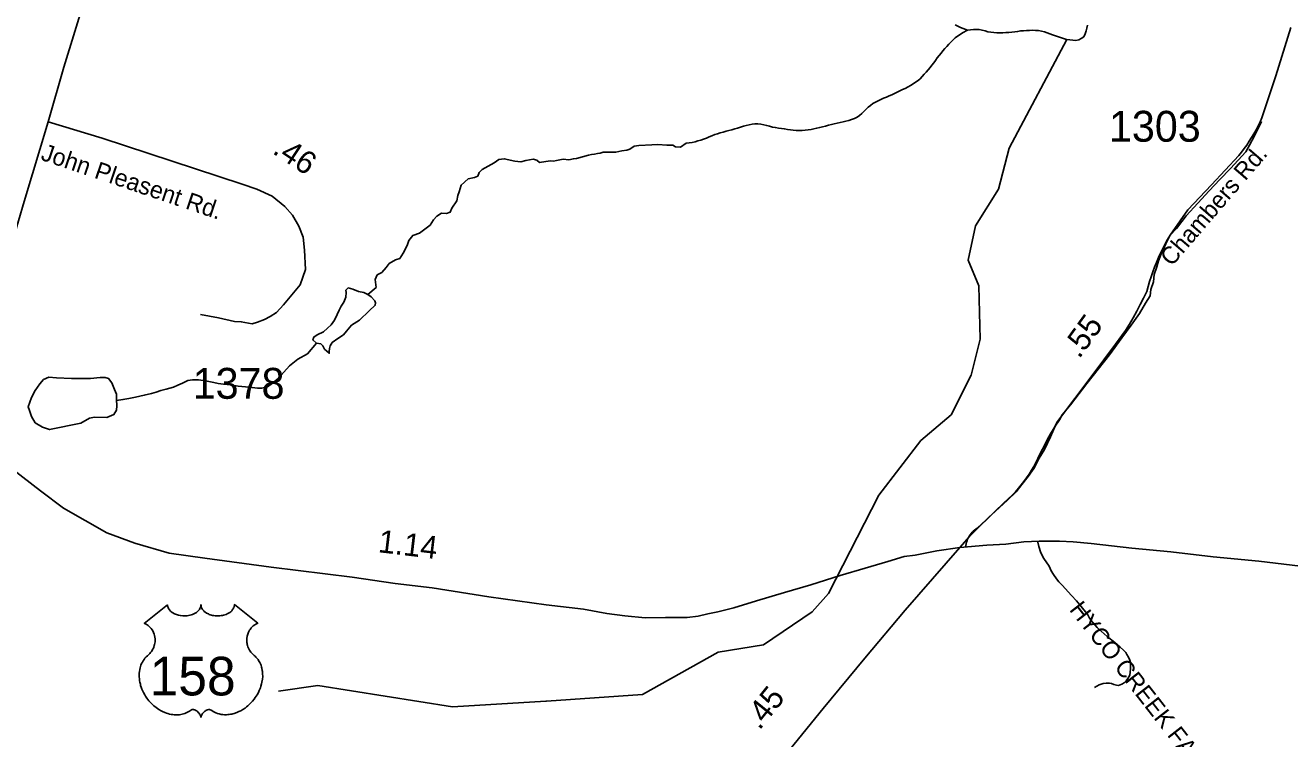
# Model space of a CAD drawing. Extents: x 1950930 to 2061844, y 904556 to 1017002.
# Drawn here: x 1960412 to 1967375, y 958442 to 962369 of the extents above; entities that cross this region are included whole.
import ezdxf

# ---------------------------------------------------------------- set-up
doc = ezdxf.new("R2010")
doc.units = 0
for name, color, linetype in [('Exist Hydrographic Creek Single Shore', 7, 'Continuous'), ('Exist Hydrographic Misc Water Feature', 7, 'Continuous'), ('Exist Road Non-System Type 51', 7, 'Continuous'), ('Exist Road Non-System Type 51 Label', 7, 'Continuous'), ('Exist Road Primary US Attributed', 7, 'Continuous'), ('Exist Road Primary US Mileage Hundredths English Label', 7, 'Continuous'), ('Exist Road Primary US Shield CELL', 7, 'Continuous'), ('Exist Road Primary US Shield Number Label', 7, 'Continuous'), ('Exist Road Primary US Structure Standard Bridge CELL', 7, 'Continuous'), ('Exist Road Secondary Type 41 Attributed', 7, 'Continuous'), ('Exist Road Secondary Type 51 Attributed', 7, 'Continuous'), ('Exist Road Secondary Type 51 Label', 7, 'Continuous'), ('Exist Road Secondary Type 51 Number Label', 7, 'Continuous')]:
    doc.layers.add(name, color=color, linetype=linetype)

msp = doc.modelspace()

# ---------------------------------------------------------------- linework, layer by layer
at = {"layer": 'Exist Hydrographic Creek Single Shore'}
for points in [[(1965531.7, 962371), (1965546.6, 962364.2), (1965561.6, 962357.3), (1965577, 962351.2), (1965599.7, 962343.4)], [(1966260.4, 962369.9), (1966257.1, 962353.5), (1966254.1, 962338), (1966248.5, 962322.6), (1966241.8, 962305.4)], [(1963281.4, 958649.7), (1963810.3, 958684.7), (1964227.3, 958918.9), (1964477.3, 958959.7), (1964744.3, 959141.3), (1964835.3, 959241.2), (1965111.3, 959783.6), (1965344.3, 960084.1), (1965511.4, 960225), (1965620.3, 960442.6), (1965670.3, 960641.8), (1965662.3, 960934.2), (1965603.2, 961076.5), (1965645.3, 961265.9), (1965770.3, 961466.8), (1965829.4, 961692.1), (1966147.8, 962290.9)], [(1965094.1, 961946), (1965108.8, 961954), (1965123.4, 961961), (1965138.6, 961967.3), (1965153.6, 961974.3), (1965168.9, 961980.5), (1965184.1, 961986.8), (1965198.9, 961993.9), (1965213.6, 962001), (1965228.4, 962008.1), (1965243.2, 962015.2), (1965258.1, 962022.1), (1965272.9, 962030.1), (1965287, 962038), (1965301.4, 962046.8), (1965314.9, 962055.5), (1965328, 962065.1), (1965339.9, 962075.5), (1965351.6, 962087.6), (1965362.7, 962099.7), (1965373.2, 962111.8), (1965383.8, 962124.7), (1965394.1, 962137.6), (1965404.5, 962150.4), (1965414.8, 962163.4), (1965424.6, 962176.3), (1965434.1, 962190.1), (1965443.9, 962203), (1965454.6, 962215.9), (1965465, 962228), (1965475.7, 962240.8), (1965487, 962252.9), (1965498, 962265), (1965509.3, 962277.1), (1965520.8, 962288.4), (1965532.7, 962299.6), (1965545.4, 962310), (1965559.3, 962318.8), (1965573.7, 962327.5), (1965599.7, 962343.4)], [(1965599.7, 962343.4), (1965616.4, 962344.6), (1965632.6, 962345.9), (1965649, 962346.4), (1965665.2, 962345.3), (1965681.1, 962341.6), (1965697.3, 962338), (1965713.1, 962333.6), (1965729.3, 962330.9), (1965745.7, 962329.6), (1965762.1, 962328.5), (1965778.5, 962328.2), (1965795, 962328.6), (1965811.4, 962329.1), (1965827.8, 962329.6), (1965844, 962330.9), (1965860.6, 962333), (1965876.8, 962336), (1965893, 962338), (1965909.2, 962339.4), (1965925.6, 962340.7), (1965942, 962341.2), (1965958.6, 962341.7), (1965974.8, 962341.3), (1965991.2, 962340.2), (1966007.6, 962337.4), (1966023.6, 962333.7), (1966039, 962328.5), (1966054.3, 962322.4), (1966069.3, 962316.4), (1966145.9, 962291.3)], [(1966145.9, 962291.3), (1966147.6, 962291), (1966164, 962289), (1966180.5, 962287), (1966196.9, 962285.8), (1966212.8, 962288.8), (1966227.2, 962295.9), (1966241.8, 962305.4)], [(1963546.1, 961659.6), (1963562.3, 961662.7), (1963578.3, 961665.7), (1963594.1, 961670.4), (1963664.8, 961671.1), (1963697, 961677.8), (1963724.8, 961682.2), (1963740.8, 961686.7), (1963765.5, 961703.4), (1963791, 961707.4), (1963862.2, 961711.4), (1963895.7, 961712.8), (1963944.1, 961710.1), (1963977.1, 961709.2), (1963991.9, 961700), (1964019.3, 961699.3), (1964050.8, 961719.8), (1964067.4, 961722), (1964083.8, 961724.8), (1964100.2, 961728.6), (1964116, 961732.4), (1964131.8, 961737.7), (1964147.2, 961743.3), (1964162.5, 961748.7), (1964177.7, 961755), (1964193.1, 961761.2), (1964208.5, 961767.4), (1964223.8, 961772), (1964239.4, 961776.6), (1964255.4, 961781.2), (1964271.4, 961785.8), (1964287, 961790.3), (1964302.8, 961794.1), (1964318.8, 961798.7), (1964334.8, 961803.4), (1964350.6, 961808), (1964366.6, 961813.4), (1964382.3, 961818), (1964398.5, 961821.7), (1964414.3, 961824.7), (1964430.3, 961826.8), (1964446.3, 961826.5), (1964462.5, 961824.5), (1964478.7, 961821.7), (1964494.7, 961817.3), (1964510.9, 961813.7), (1964526.9, 961809.2), (1964543.1, 961806.4), (1964559.5, 961803.6), (1964575.9, 961801.7), (1964592.3, 961798.8), (1964608.7, 961796.1), (1964624.9, 961794), (1964641.3, 961792.1), (1964657.7, 961791), (1964673.9, 961790.6), (1964690.1, 961790.2), (1964706.3, 961791.6), (1964722.5, 961793.7), (1964738.7, 961796.6), (1964754.7, 961799.6), (1964770.7, 961803.4), (1964786.9, 961807.2), (1964802.9, 961810.9), (1964818.7, 961814.6), (1964834.9, 961819.3), (1964851.1, 961823), (1964866.9, 961826.8), (1964882.9, 961830.5), (1964899.1, 961833.6), (1964915.1, 961837.3), (1964930.9, 961841.9), (1964946.7, 961845.7), (1964962.4, 961850.2), (1964977.8, 961855.6), (1964992.6, 961863.6), (1965005.9, 961873.2), (1965018.4, 961883.5), (1965030.3, 961894.8), (1965042, 961906.9), (1965053.9, 961918.1), (1965066.4, 961928.5), (1965079.7, 961938.1), (1965094.1, 961946)], [(1962299.1, 960887.4), (1962343.5, 960926.7), (1962339.5, 960969.7), (1962350.2, 960995.2), (1962376.4, 961008.7), (1962399.2, 961035.6), (1962416.7, 961058.4), (1962451.6, 961078.6), (1962474.4, 961085.3), (1962493.2, 961114.8), (1962515.4, 961157.8), (1962525, 961184.4), (1962545.3, 961212.3), (1962582.5, 961225), (1962612.1, 961246.5), (1962641.6, 961269.4), (1962660.4, 961298.9), (1962679.2, 961317.7), (1962703.4, 961335.2), (1962732.2, 961333.8), (1962752.4, 961340.6), (1962760.4, 961363.4), (1962788.6, 961403.7), (1962794, 961431.9), (1962800.7, 961453.4), (1962812.1, 961489.7), (1962851.1, 961523.3), (1962886, 961531.4), (1962903.4, 961538.1), (1962911.5, 961558.2), (1962927.6, 961575.7), (1962993.4, 961612), (1963018.9, 961630.8), (1963049.8, 961634.8), (1963107.5, 961621.4), (1963140.7, 961617.2), (1963168.6, 961625.2), (1963209.5, 961631.9), (1963229.7, 961626.8), (1963244.5, 961614.7), (1963302.2, 961622.7), (1963320.5, 961622.1), (1963336.7, 961624.3), (1963373.4, 961632.1), (1963405.6, 961629.5), (1963430.5, 961634.6), (1963446.9, 961635.2), (1963514, 961655.1), (1963530.2, 961657.5), (1963546.1, 961659.6)], [(1963278.6, 958649.5), (1962764.3, 958617.7), (1962023.2, 958734.8), (1961806.3, 958703.2)], [(1963281.4, 958649.7), (1963278.6, 958649.5)]]:
    msp.add_lwpolyline(points, dxfattribs=at)
at = {"layer": 'Exist Hydrographic Misc Water Feature'}
for points in [[(1962015.2, 960619), (1961995.1, 960637.8), (1962000.5, 960652.6), (1962019.3, 960664.7), (1962054.2, 960682.2), (1962075.6, 960702.3), (1962095.8, 960721.1), (1962114.6, 960746.7), (1962129.4, 960777.6), (1962141.4, 960801.8), (1962152.2, 960823.3), (1962165.6, 960846.1), (1962176.4, 960873), (1962179, 960898.5), (1962177.7, 960911.9), (1962189.8, 960924), (1962216.6, 960917.3), (1962247.5, 960903.9), (1962277.1, 960898.5), (1962298.5, 960887.7), (1962317.3, 960874.3), (1962336.1, 960852.8), (1962341.5, 960840.7), (1962338.8, 960828.6), (1962305.3, 960797.7), (1962252.9, 960746.7), (1962208.6, 960718.4), (1962181.7, 960684.9), (1962164.3, 960666), (1962133.4, 960644.5), (1962101.2, 960623), (1962090.4, 960605.6), (1962087.7, 960590.8), (1962086.4, 960573.3), (1962086.4, 960563.9), (1962059.5, 960586.8), (1962050.1, 960605.6), (1962039.4, 960616.3)], [(1960446.2, 960320.7), (1960466.4, 960358.3), (1960491.9, 960396), (1960513.4, 960420.2), (1960541.6, 960432.2), (1960584.5, 960428.2), (1960666.4, 960425.5), (1960771.2, 960425.5), (1960824.9, 960429.6), (1960851.7, 960430.9), (1960870.5, 960425.5), (1960888, 960401.3), (1960902.8, 960365.1), (1960914.9, 960338.2), (1960914.9, 960308.6), (1960916.2, 960273.7), (1960914.9, 960250.9), (1960900.1, 960226.7), (1960861.1, 960210.5), (1960794, 960211.9), (1960765.8, 960206.5), (1960717.5, 960179.6), (1960545.6, 960143.4), (1960506.7, 960156.8), (1960466.4, 960181), (1960446.2, 960215.9), (1960435.5, 960248.2), (1960427.4, 960269.7)]]:
    msp.add_lwpolyline(points, close=True, dxfattribs=at)
msp.add_lwpolyline([(1960914.5, 960304.6), (1960949.6, 960308.7), (1960981.6, 960314.7), (1961019.5, 960322.7), (1961067.5, 960332.6), (1961107.5, 960342.5), (1961133.7, 960350.4), (1961157.7, 960358.4), (1961187.6, 960366.4), (1961227.6, 960378.2), (1961251.6, 960388.2), (1961277.7, 960400.2), (1961307.8, 960414.1), (1961333.8, 960418.1), (1961365.8, 960417.9), (1961403.8, 960411.9), (1961449.7, 960403.9), (1961473.7, 960397.8), (1961503.6, 960393.7), (1961541.8, 960389.6), (1961583.6, 960383.6), (1961625.6, 960379.6), (1961661.7, 960375.4), (1961691.7, 960371.4), (1961713.8, 960371.4), (1961745.8, 960379.3), (1961773.7, 960399.3), (1961803.8, 960425.2), (1961866.2, 960495.4), (1961913.2, 960531.7), (1961966.9, 960561.2), (1962015.2, 960619)], dxfattribs=at)
at = {"layer": 'Exist Road Non-System Type 51'}
for points in [[(1965590.8, 959497.5), (1965591.6, 959506.4), (1965593.1, 959515.3), (1965595.2, 959524.1), (1965597.9, 959532.7), (1965601.2, 959541.1), (1965605.1, 959549.3), (1965609.5, 959557.2), (1965614.4, 959564.7), (1965619.9, 959571.9), (1965625.8, 959578.7), (1965632.2, 959585.1), (1965639, 959591), (1965646.2, 959596.5), (1965653.8, 959601.4), (1965703.2, 959647.2), (1965751.2, 959692.9), (1965799.2, 959738.5), (1965847.5, 959783.9), (1965864.2, 959801.9), (1965880.4, 959820.4), (1965895.9, 959839.3), (1965910.9, 959858.8), (1965925.2, 959878.6), (1965939.1, 959899), (1965952.2, 959919.7), (1965964.8, 959940.8), (1965976.8, 959962.3), (1965987.9, 959984.1), (1966004.8, 960018.7), (1966022.1, 960053), (1966039.9, 960087), (1966058.2, 960120.8), (1966077, 960154.3), (1966096.2, 960187.6), (1966286.6, 960442.3), (1966414.8, 960614.7), (1966470.9, 960689), (1966491.8, 960724.3), (1966512.2, 960759.8), (1966532.1, 960795.6), (1966551.5, 960831.7), (1966570.4, 960868), (1966588.8, 960904.6), (1966595.8, 960931.7), (1966603.2, 960958.7), (1966611.6, 960985.5), (1966620.5, 961012), (1966630.2, 961038.3), (1966640.5, 961064.4), (1966651.6, 961090.2), (1966663.2, 961115.6), (1966675.6, 961140.8), (1966688.6, 961165.6), (1966702.2, 961190.1), (1966716.5, 961214.2), (1966813.4, 961353.6), (1966944.2, 961490.2), (1967094, 961651.9), (1967109.2, 961671), (1967124.1, 961690.4), (1967138.2, 961710.3), (1967151.9, 961730.6), (1967165, 961751.2), (1967177.5, 961772.2), (1967189.4, 961793.5), (1967200.8, 961815.1), (1967211.4, 961837), (1967221.4, 961859.1), (1967298, 962091.4), (1967380.5, 962357.8)], [(1965987.1, 959524), (1965993.2, 959499.7), (1966004.1, 959466), (1966021.4, 959434.9), (1966049.4, 959391.8), (1966060.9, 959365.9), (1966073.5, 959346.3), (1966089.6, 959322.1), (1966103.1, 959306.2), (1966121, 959286.7), (1966172.5, 959229.8), (1966200.1, 959201.2), (1966218.5, 959179.1), (1966241, 959152.3), (1966251.4, 959139.6), (1966260.6, 959127), (1966270.1, 959108.9), (1966279.6, 959093.9), (1966291.6, 959079.8), (1966313.9, 959055), (1966336.9, 959034), (1966370.2, 959005.5), (1966412.5, 958971.2), (1966441.9, 958946.5), (1966460, 958929), (1966471.9, 958915.8), (1966478.1, 958906.2), (1966486.2, 958891.6), (1966493.8, 958875.4), (1966497.8, 958860.8), (1966498.2, 958842.9), (1966498.6, 958827.4), (1966496.9, 958808.9), (1966493.4, 958792.2), (1966483.4, 958774.1), (1966473.5, 958760.6), (1966463.1, 958750.6), (1966451.1, 958741.6), (1966441.9, 958737.9), (1966432.1, 958735.3), (1966420.6, 958737), (1966406.8, 958740.8), (1966393.9, 958745.9), (1966382, 958748.2), (1966365, 958748.5), (1966347.5, 958745.4), (1966326.2, 958739), (1966299.8, 958724.9)]]:
    msp.add_lwpolyline(points, dxfattribs=at)
at = {"layer": 'Exist Road Primary US Attributed'}
for points in [[(1960342.4, 959926.3), (1960496, 959807.1), (1960622.1, 959710.5), (1960861.4, 959575.5), (1961016.2, 959518.2), (1961205.2, 959464.3), (1961400.7, 959436.3), (1961765.8, 959386.7), (1962212.8, 959331.4), (1962448.2, 959296.6), (1962651.8, 959272.3), (1962964.9, 959223.8), (1963279.7, 959179.3), (1963485.3, 959154.9), (1963615.2, 959130.8), (1963713.2, 959118.8), (1963825.2, 959106.7), (1963937.3, 959108.7), (1963995.3, 959108.7), (1964057.3, 959108.7), (1964117.3, 959116.4), (1964171.4, 959128.7), (1964225.2, 959140.6), (1964313.3, 959162.6), (1964439.3, 959200.6), (1964593.3, 959246.4), (1964737.3, 959288.4), (1964899.4, 959340.3), (1965037.5, 959380.3), (1965161.3, 959418.3), (1965251.5, 959444.3), (1965311.4, 959452.2), (1965431.4, 959476.1), (1965557.4, 959494.1)], [(1965557.4, 959494.1), (1965707.3, 959508), (1965811.5, 959513.9), (1965911.4, 959526), (1965995.5, 959529.9), (1966107.3, 959529.8), (1966181.5, 959525.8), (1966281.5, 959515.8), (1966505.5, 959491.7), (1966719.3, 959471.7), (1966953.4, 959443.6), (1967205.4, 959419.4), (1967525.3, 959381.4), (1967835.3, 959355.3), (1967991.2, 959347.1), (1968198.1, 959313.4), (1968343.2, 959296.1)]]:
    msp.add_lwpolyline(points, dxfattribs=at)
at = {"layer": 'Exist Road Primary US Shield CELL'}
msp.add_lwpolyline([(1961195.4, 959179.7), (1961195.8, 959174.3), (1961197.1, 959168), (1961198.1, 959164.8), (1961201, 959158.5), (1961205.9, 959151.2), (1961212.7, 959144), (1961220.4, 959137.6), (1961225.5, 959134.3), (1961234.3, 959129.6), (1961244.2, 959125.4), (1961255.3, 959122.2), (1961266.6, 959119.9), (1961279, 959118.6), (1961291.2, 959118.3), (1961304.5, 959119.3), (1961319, 959122.1), (1961325.8, 959123.9), (1961333.3, 959126.5), (1961340.3, 959129.4), (1961348, 959133.5), (1961354.1, 959137.4), (1961359, 959140.9), (1961365.8, 959147.4), (1961371.2, 959154.2), (1961373.5, 959158), (1961375.5, 959161.7), (1961378.2, 959169.4), (1961378.9, 959172.8), (1961379.5, 959179.9), (1961379.9, 959174), (1961380.5, 959170.2), (1961381.5, 959166.6), (1961383, 959162.7), (1961385.8, 959157.2), (1961388.8, 959152.7), (1961394.5, 959145.9), (1961398.1, 959142.6), (1961401.4, 959139.9), (1961410.1, 959133.9), (1961420.3, 959128.8), (1961425.3, 959126.5), (1961430.5, 959124.7), (1961437, 959122.7), (1961443.8, 959121.2), (1961450.5, 959120), (1961457.3, 959119), (1961464.3, 959118.5), (1961470, 959118.3), (1961477, 959118.4), (1961483.4, 959118.8), (1961490, 959119.6), (1961497.3, 959120.8), (1961503.2, 959122.1), (1961510.9, 959124.1), (1961517.9, 959126.6), (1961524.1, 959129.3), (1961532, 959133.5), (1961538.5, 959137.5), (1961543.2, 959141.3), (1961548.8, 959146.5), (1961554.1, 959152.6), (1961557.3, 959157.1), (1961559.5, 959161.7), (1961561.5, 959166.6), (1961562.8, 959171.8), (1961563.4, 959176.2), (1961563.5, 959180.1), (1961692.1, 959077.6), (1961689.1, 959076.5), (1961682.1, 959073.1), (1961676.5, 959069.8), (1961667.7, 959063.6), (1961663.9, 959060.1), (1961660.1, 959056.6), (1961656.6, 959052.8), (1961653.5, 959049.2), (1961649.8, 959044), (1961646.5, 959038.9), (1961643.2, 959033.2), (1961640.8, 959028.2), (1961636.8, 959017.9), (1961634.9, 959011.3), (1961633.7, 959005.8), (1961632.2, 958994.3), (1961631.8, 958988.9), (1961631.8, 958983.5), (1961632.1, 958977.8), (1961632.7, 958972.3), (1961633.7, 958966.6), (1961634.6, 958961.6), (1961636.2, 958955.4), (1961638.4, 958948.3), (1961641.3, 958941.4), (1961647.1, 958930.2), (1961654.7, 958918.8), (1961660.1, 958912.4), (1961665.4, 958906.9), (1961673.3, 958900.3), (1961677.6, 958896.5), (1961682.6, 958891.5), (1961690.6, 958882.2), (1961693.9, 958877.8), (1961697.2, 958872.8), (1961700.2, 958867.7), (1961703.3, 958862.3), (1961705.7, 958857.5), (1961710.2, 958846.5), (1961713.5, 958835.7), (1961715, 958830.1), (1961717.4, 958817.5), (1961718.3, 958811.3), (1961719.3, 958799), (1961719.4, 958784.1), (1961718.2, 958769.9), (1961715.6, 958753.5), (1961713.4, 958743.6), (1961710, 958732.1), (1961706.7, 958722.1), (1961700.8, 958707.5), (1961695.6, 958696.8), (1961688.9, 958684.4), (1961684.2, 958676.9), (1961678.8, 958668.8), (1961672.1, 958659.5), (1961664.2, 958649.7), (1961654.7, 958639.2), (1961647, 958631.6), (1961637, 958622.6), (1961630.9, 958617.6), (1961622.3, 958611.1), (1961610.4, 958603.1), (1961598.7, 958596.4), (1961588.8, 958591.3), (1961580, 958587.5), (1961568.6, 958583.2), (1961549.6, 958577.9), (1961542.7, 958576.5), (1961534.5, 958575.3), (1961526.8, 958574.5), (1961519.4, 958574), (1961509.3, 958574), (1961499.4, 958574.8), (1961490, 958576.2), (1961480.2, 958578.2), (1961469.9, 958581.3), (1961460.6, 958584.9), (1961451.2, 958589.5), (1961435.3, 958599.6), (1961430.7, 958602), (1961428.1, 958602.7), (1961422, 958603), (1961416.2, 958601.8), (1961410.3, 958599.4), (1961406.7, 958597.5), (1961401.9, 958594.4), (1961398.3, 958591.5), (1961393.9, 958587.3), (1961390.9, 958583.8), (1961388.5, 958581.1), (1961384.1, 958574), (1961382.5, 958570.7), (1961380.8, 958566.4), (1961379.3, 958560), (1961377.3, 958568), (1961374.9, 958573.4), (1961372.2, 958577.9), (1961369.4, 958581.9), (1961364.9, 958587.1), (1961360.9, 958591), (1961356, 958594.9), (1961350.8, 958598.1), (1961346.7, 958600.2), (1961342.9, 958601.6), (1961338.3, 958602.8), (1961334.5, 958603.1), (1961331.4, 958603), (1961327.1, 958602), (1961321.2, 958597.8), (1961315.7, 958594), (1961309.7, 958590.3), (1961302.6, 958586.5), (1961297.4, 958584.1), (1961291.1, 958581.6), (1961283.8, 958579.2), (1961275.9, 958577.2), (1961267.8, 958575.6), (1961260.7, 958574.4), (1961253, 958573.7), (1961246.1, 958573.5), (1961238.9, 958573.6), (1961232.1, 958574.1), (1961224.3, 958574.8), (1961214.6, 958576.2), (1961206.5, 958578.1), (1961198, 958580.4), (1961189.3, 958583.1), (1961180, 958586.7), (1961168.3, 958591.7), (1961160.1, 958595.9), (1961147.3, 958603.3), (1961132.3, 958613.7), (1961120.9, 958622.9), (1961112.6, 958630.4), (1961100.4, 958642.9), (1961093.2, 958651), (1961081.9, 958665.6), (1961074.7, 958676.2), (1961070, 958683.9), (1961063.2, 958696.4), (1961059.4, 958704.2), (1961054.6, 958715.6), (1961050.7, 958726), (1961047.5, 958735.9), (1961045.8, 958742.2), (1961043.4, 958753.2), (1961041.9, 958761), (1961040.5, 958771.8), (1961039.7, 958783.1), (1961039.5, 958793.5), (1961039.8, 958802.2), (1961040.8, 958812.3), (1961042.5, 958823), (1961044.5, 958832.2), (1961046.4, 958838.8), (1961049.1, 958846.8), (1961052.7, 958855.7), (1961057, 958864.2), (1961061.1, 958871.3), (1961066.1, 958878.9), (1961071.2, 958885.4), (1961077.7, 958892.5), (1961084.6, 958899), (1961090.8, 958904.1), (1961098.3, 958911.4), (1961102.1, 958915.8), (1961106.8, 958922), (1961110.5, 958927.7), (1961113.5, 958932.8), (1961117.4, 958940.3), (1961119.8, 958945.9), (1961122.7, 958954.6), (1961124.2, 958960.7), (1961125.7, 958968.5), (1961126.7, 958975.9), (1961127.1, 958985.1), (1961126.9, 958992.7), (1961125.9, 959001.5), (1961124.2, 959010.1), (1961122.2, 959017.5), (1961119, 959026), (1961116.1, 959032.2), (1961111.1, 959040.7), (1961105.7, 959048.5), (1961100, 959054.9), (1961094.3, 959060.6), (1961088.9, 959064.8), (1961083.7, 959068.6), (1961077.1, 959072.5), (1961070.8, 959075.6), (1961066.9, 959077.2)], close=True, dxfattribs=at)
at = {"layer": 'Exist Road Secondary Type 41 Attributed'}
for points in [[(1960538.2, 961837.7), (1960836.3, 961747.7), (1961605.7, 961495.1), (1961687.6, 961466.9), (1961772.2, 961427.9), (1961842, 961371.5), (1961883.6, 961324.4), (1961918.5, 961264), (1961942, 961202.2), (1961950.1, 961132.3), (1961955.5, 961024.8), (1961925.3, 960941.5), (1961833.7, 960829.9), (1961796.4, 960788.3), (1961760.1, 960765.5), (1961729.2, 960749.4), (1961691.6, 960734.6), (1961660.7, 960726.5), (1961601.7, 960737.3), (1961563.7, 960739.4), (1961476.1, 960759.2), (1961376.4, 960777.3)], [(1964042.6, 957672.9), (1964065.6, 957702), (1964100.5, 957744.9), (1964196.6, 957864.7), (1964378.8, 958082.6), (1964598.8, 958352.6), (1964805, 958608.4), (1965035, 958886.3), (1965257.2, 959150.2), (1965557.4, 959494.1)]]:
    msp.add_lwpolyline(points, dxfattribs=at)
at = {"layer": 'Exist Road Secondary Type 51 Attributed'}
for points in [[(1960538.2, 961837.7), (1960624.3, 962139.4), (1960753, 962556.9), (1960869.2, 962952.7), (1960989.4, 963346.3), (1961088.3, 963784), (1961318.9, 964478), (1961466.7, 964949.1), (1961550.2, 965215.5), (1961673.3, 965553.1)], [(1959901.7, 960322), (1959969.1, 960390.3), (1960033, 960458.6), (1960101.2, 960539.2), (1960167.1, 960640.2), (1960210.6, 960709.4), (1960245, 960824.7), (1960312.3, 961079.4), (1960406.9, 961399.6), (1960538.2, 961837.7)], [(1965557.4, 959494.1), (1965611.7, 959555.8), (1965649.7, 959593.9), (1965731.8, 959673.8), (1965819.9, 959755.8), (1965867.9, 959801.8), (1965899.9, 959841.8), (1965933.8, 959885.7), (1965965.9, 959929.6), (1965995.9, 959985.6), (1966023.9, 960033.7), (1966058, 960103.6), (1966084, 960161.7), (1966107.9, 960197.6), (1966121.9, 960225.7), (1966168.1, 960279.6), (1966258.1, 960397.6), (1966382.2, 960555.4), (1966450.2, 960649.5), (1966502.3, 960719.4), (1966548.2, 960783.5), (1966580.2, 960839.4), (1966606.2, 960879.3), (1966610.4, 960915.4), (1966624.3, 960957.4), (1966628.3, 960997.3), (1966642.4, 961039.4), (1966652.5, 961073.2), (1966666.5, 961111.4), (1966684.5, 961149.4), (1966700.4, 961183.3), (1966716.4, 961213.4), (1966750.4, 961251.3), (1966804.4, 961321.2), (1966868.5, 961389.3), (1966930.5, 961457.2), (1966990.7, 961521.2), (1967048.7, 961581), (1967090.7, 961627.2), (1967132.6, 961673.1), (1967152.6, 961709.1), (1967180.7, 961760.9), (1967218.7, 961839)]]:
    msp.add_lwpolyline(points, dxfattribs=at)

# ---------------------------------------------------------------- texts
at = {"layer": 'Exist Road Non-System Type 51 Label'}
msp.add_text('  HYCO CREEK FARM RD', height=95, rotation=307.99873, dxfattribs=at).set_placement((1966114, 959207.2))
at = {"layer": 'Exist Road Primary US Mileage Hundredths English Label'}
msp.add_text('1.14', height=125, rotation=353.19349, dxfattribs=at).set_placement((1962351.3, 959469.3))
at = {"layer": 'Exist Road Primary US Shield Number Label'}
msp.add_text('158', height=212.5, dxfattribs=at).set_placement((1961096.6, 958680.4))
at = {"layer": 'Exist Road Primary US Structure Standard Bridge CELL'}
for s, rotation, p in [('.46', 326.56801, (1961767.9, 961667.6)), ('.55', 54.13725, (1966215.6, 960529.6)), ('.45', 51.13468, (1964454.9, 958485))]:
    msp.add_text(s, height=125, rotation=rotation, dxfattribs=at).set_placement(p)
at = {"layer": 'Exist Road Secondary Type 51 Label'}
for s, rotation, p in [('John Pleasent Rd.', 341.38212, (1960492.4, 961630.1)), ('Chambers Rd.', 49.33718, (1966724.9, 961038))]:
    msp.add_text(s, height=95, rotation=rotation, dxfattribs=at).set_placement(p)
at = {"layer": 'Exist Road Secondary Type 51 Number Label'}
for s, p in [('1303', (1966379.1, 961728.4)), ('1378', (1961334, 960313.3))]:
    msp.add_text(s, height=170, dxfattribs=at).set_placement(p)

doc.saveas('drawing.dxf')
